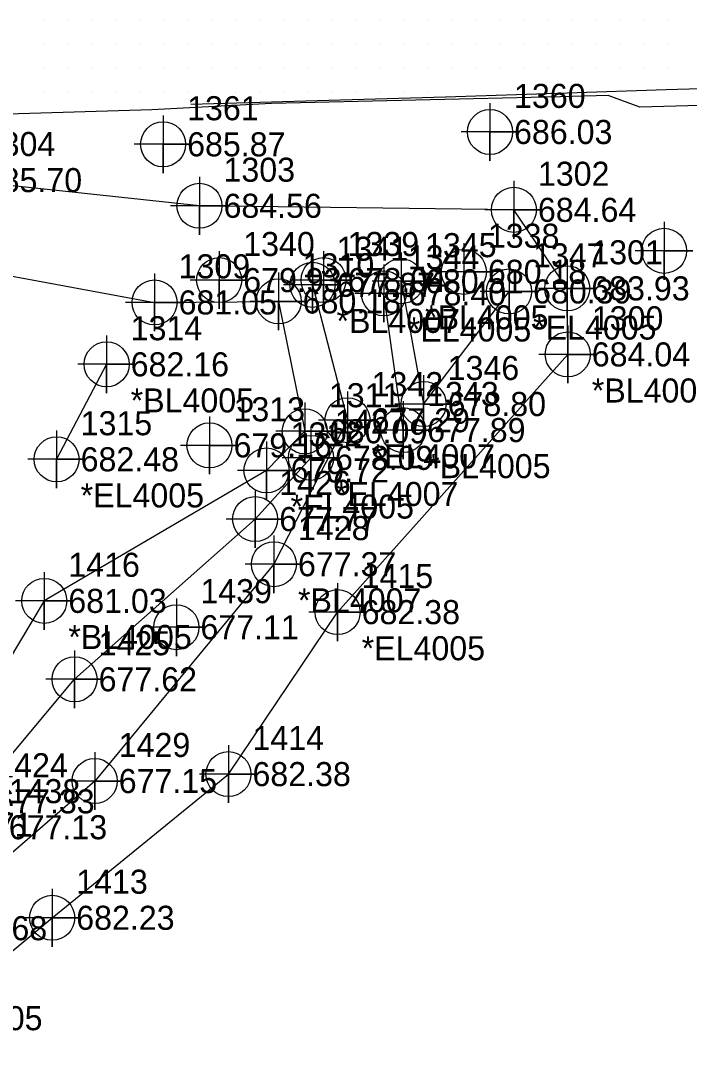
# Model space of a CAD drawing. Extents: x 1755643 to 1760494, y 736519 to 737621.
# Drawn here: x 1759051.4 to 1759120.9, y 736912 to 737018.8 of the extents above; entities that cross this region are included whole.
import ezdxf

# ---------------------------------------------------------------- set-up
doc = ezdxf.new("R2010")
doc.units = 0
for name, color, linetype in [('Exist Horizontal Alignment Curve and Spiral Data', 7, 'Continuous'), ('Exist Horizontal Alignment Direction Label', 7, 'Continuous'), ('Exist Roads EOT', 7, 'Continuous'), ('Exist Utilities Sanitary Sewer UG Line', 7, 'Continuous'), ('Old_Level_3', 7, 'Continuous'), ('Prop Conc 5in Monolithic Keyed In Island', 7, 'Continuous'), ('Prop Corridor Linear Feature', 7, 'Continuous'), ('Prop EOT Dash', 7, 'Continuous'), ('Prop Horizontal Alignment Station Label', 7, 'Continuous'), ('Prop Horizontal Alignment Tick Label', 7, 'Continuous'), ('Prop Horizontal Alignment Tick Large', 7, 'Continuous'), ('Prop Horizontal Alignment Tick Small', 7, 'Continuous'), ('Prop Lane Lines', 7, 'Continuous'), ('Prop Paved Shoulder', 7, 'Continuous'), ('Prop Superelevation Label', 7, 'Continuous'), ('Prop Terminator CELL', 7, 'Continuous'), ('Scratch_Level_1', 7, 'Continuous'), ('Scratch_Level_2', 7, 'Continuous'), ('Scratch_Level_5', 7, 'Continuous'), ('Scratch_Level_9', 7, 'Continuous')]:
    doc.layers.add(name, color=color, linetype=linetype)

msp = doc.modelspace()

# ---------------------------------------------------------------- linework, layer by layer
at = {"layer": 'Exist Horizontal Alignment Curve and Spiral Data'}
for points in [[(1759100.17, 737010.17), (1759100.17, 737004.17), (1759100.17, 737007.17), (1759103.17, 737007.17), (1759097.17, 737007.17)], [(1759066.19, 737008.89), (1759066.19, 737002.89), (1759066.19, 737005.89), (1759069.19, 737005.89), (1759063.19, 737005.89)], [(1759118.27, 736997.82), (1759118.27, 736991.82), (1759118.27, 736994.82), (1759121.27, 736994.82), (1759115.27, 736994.82)], [(1759097.45, 736995.63), (1759097.45, 736989.63), (1759097.45, 736992.63), (1759100.45, 736992.63), (1759094.45, 736992.63)], [(1759072.02, 736994.78), (1759072.02, 736988.78), (1759072.02, 736991.78), (1759075.02, 736991.78), (1759069.02, 736991.78)], [(1759071.01, 736977.61), (1759071.01, 736971.61), (1759071.01, 736974.61), (1759074.01, 736974.61), (1759068.01, 736974.61)]]:
    msp.add_lwpolyline(points, dxfattribs=at)
for centre in [(1759100.17, 737007.17), (1759066.19, 737005.89), (1759118.27, 736994.82), (1759097.45, 736992.63), (1759072.02, 736991.78), (1759071.01, 736974.61)]:
    msp.add_circle(centre, 2.34, dxfattribs=at)
at = {"layer": 'Prop Corridor Linear Feature'}
msp.add_lwpolyline([(1759145.67, 737011.05), (1759130.72, 737010.15), (1759115.74, 737009.75), (1759112.46, 737010.95), (1759107.45, 737010.81)], dxfattribs=at)
at = {"layer": 'Prop Horizontal Alignment Station Label'}
for points in [[(1759082.87, 736994.78), (1759082.87, 736988.78), (1759082.87, 736991.78), (1759085.87, 736991.78), (1759079.87, 736991.78)], [(1759067.57, 736958.71), (1759067.57, 736952.71), (1759067.57, 736955.71), (1759070.57, 736955.71), (1759064.57, 736955.71)]]:
    msp.add_lwpolyline(points, dxfattribs=at)
for centre in [(1759082.87, 736991.78), (1759067.57, 736955.71)]:
    msp.add_circle(centre, 2.34, dxfattribs=at)
at = {"layer": 'Prop Horizontal Alignment Tick Small'}
for points in [[(1759081.72, 736994.29), (1759081.72, 736988.29), (1759081.72, 736991.29), (1759084.72, 736991.29), (1759078.72, 736991.29)], [(1759085.36, 736980.22), (1759085.36, 736974.22), (1759085.36, 736977.22), (1759088.36, 736977.22), (1759082.36, 736977.22)], [(1759081.56, 736976.31), (1759081.56, 736970.31), (1759081.56, 736973.31), (1759084.56, 736973.31), (1759078.56, 736973.31)], [(1759075.76, 736969.95), (1759075.76, 736963.95), (1759075.76, 736966.95), (1759078.76, 736966.95), (1759072.76, 736966.95)], [(1759077.71, 736965.26), (1759077.71, 736959.26), (1759077.71, 736962.26), (1759080.71, 736962.26), (1759074.71, 736962.26)], [(1759056.99, 736953.3), (1759056.99, 736947.3), (1759056.99, 736950.3), (1759059.99, 736950.3), (1759053.99, 736950.3)], [(1759059.08, 736942.73), (1759059.08, 736936.73), (1759059.08, 736939.73), (1759062.08, 736939.73), (1759056.08, 736939.73)]]:
    msp.add_lwpolyline(points, dxfattribs=at)
for centre in [(1759081.72, 736991.29), (1759085.36, 736977.22), (1759081.56, 736973.31), (1759075.76, 736966.95), (1759077.71, 736962.26), (1759056.99, 736950.3), (1759059.08, 736939.73)]:
    msp.add_circle(centre, 2.34, dxfattribs=at)
at = {"layer": 'Prop Lane Lines'}
for points in [[(1759069.97, 737002.5), (1759069.97, 736996.5), (1759069.97, 736999.5), (1759072.97, 736999.5), (1759066.97, 736999.5)], [(1759102.65, 737002.08), (1759102.65, 736996.08), (1759102.65, 736999.08), (1759105.65, 736999.08), (1759099.65, 736999.08)], [(1759090.92, 736994.66), (1759090.92, 736988.66), (1759090.92, 736991.66), (1759093.92, 736991.66), (1759087.92, 736991.66)], [(1759102.15, 736993.6), (1759102.15, 736987.6), (1759102.15, 736990.6), (1759105.15, 736990.6), (1759099.15, 736990.6)], [(1759108.2, 736993.92), (1759108.2, 736987.92), (1759108.2, 736990.92), (1759111.2, 736990.92), (1759105.2, 736990.92)], [(1759065.3, 736992.46), (1759065.3, 736986.46), (1759065.3, 736989.46), (1759068.3, 736989.46), (1759062.3, 736989.46)], [(1759078.2, 736992.57), (1759078.2, 736986.57), (1759078.2, 736989.57), (1759081.2, 736989.57), (1759075.2, 736989.57)], [(1759089.13, 736993.4), (1759089.13, 736987.4), (1759089.13, 736990.4), (1759092.13, 736990.4), (1759086.13, 736990.4)], [(1759108.25, 736987.06), (1759108.25, 736981.06), (1759108.25, 736984.06), (1759111.25, 736984.06), (1759105.25, 736984.06)], [(1759060.32, 736986.03), (1759060.32, 736980.03), (1759060.32, 736983.03), (1759063.32, 736983.03), (1759057.32, 736983.03)], [(1759093.27, 736981.9), (1759093.27, 736975.9), (1759093.27, 736978.9), (1759096.27, 736978.9), (1759090.27, 736978.9)], [(1759080.92, 736979.07), (1759080.92, 736973.07), (1759080.92, 736976.07), (1759083.92, 736976.07), (1759077.92, 736976.07)], [(1759091.14, 736979.19), (1759091.14, 736973.19), (1759091.14, 736976.19), (1759094.14, 736976.19), (1759088.14, 736976.19)], [(1759055.12, 736976.16), (1759055.12, 736970.16), (1759055.12, 736973.16), (1759058.12, 736973.16), (1759052.12, 736973.16)], [(1759076.94, 736975), (1759076.94, 736969), (1759076.94, 736972), (1759079.94, 736972), (1759073.94, 736972)], [(1759053.84, 736961.45), (1759053.84, 736955.45), (1759053.84, 736958.45), (1759056.84, 736958.45), (1759050.84, 736958.45)], [(1759084.33, 736960.28), (1759084.33, 736954.28), (1759084.33, 736957.28), (1759087.33, 736957.28), (1759081.33, 736957.28)], [(1759072.98, 736943.45), (1759072.98, 736937.45), (1759072.98, 736940.45), (1759075.98, 736940.45), (1759069.98, 736940.45)], [(1759054.66, 736928.52), (1759054.66, 736922.52), (1759054.66, 736925.52), (1759057.66, 736925.52), (1759051.66, 736925.52)]]:
    msp.add_lwpolyline(points, dxfattribs=at)
for centre in [(1759069.97, 736999.5), (1759102.65, 736999.08), (1759090.92, 736991.66), (1759089.13, 736990.4), (1759102.15, 736990.6), (1759108.2, 736990.92), (1759065.3, 736989.46), (1759078.2, 736989.57), (1759108.25, 736984.06), (1759060.32, 736983.03), (1759093.27, 736978.9), (1759091.14, 736976.19), (1759080.92, 736976.07), (1759055.12, 736973.16), (1759076.94, 736972), (1759053.84, 736958.45), (1759084.33, 736957.28), (1759072.98, 736940.45), (1759054.66, 736925.52)]:
    msp.add_circle(centre, 2.34, dxfattribs=at)
at = {"layer": 'Prop Terminator CELL'}
msp.add_line((1759081.72, 736991.29), (1759085.36, 736977.22), dxfattribs=at)
for points in [[(1759085.36, 736977.22), (1759077.71, 736962.26), (1759059.08, 736939.73), (1759041.42, 736924.44), (1759026.52, 736914.34), (1759015.82, 736906.96), (1758998.09, 736890.9)], [(1758994.95, 736898.07), (1759015.63, 736913.87), (1759033.04, 736926.27), (1759046.35, 736937.62), (1759056.99, 736950.3), (1759075.76, 736966.95), (1759081.56, 736973.31)]]:
    msp.add_lwpolyline(points, dxfattribs=at)
at = {"layer": 'Scratch_Level_1'}
for points in [[(1759107.45, 737010.81), (1759092.46, 737010.47), (1759077.46, 737010.12), (1759065.02, 737009.48)], [(1759065.02, 737009.48), (1759050.02, 737009.03), (1759029.86, 737008.36), (1759020.04, 737008.1), (1759005.05, 737007.39), (1758990.06, 737006.95), (1758975.04, 737006.42), (1758960.05, 737006), (1758945.06, 737005.7), (1758930.12, 737005.23), (1758915.13, 737004.67), (1758900.15, 737004.23), (1758885.1, 737003.7), (1758867.07, 737003.45)]]:
    msp.add_lwpolyline(points, dxfattribs=at)
at = {"layer": 'Scratch_Level_2'}
for p, q in [((1759053.75, 737018.75), (1759053.75, 737018.75)), ((1759056.25, 737018.75), (1759056.25, 737018.75)), ((1759058.75, 737018.75), (1759058.75, 737018.75)), ((1759061.25, 737018.75), (1759061.25, 737018.75)), ((1759063.75, 737018.75), (1759063.75, 737018.75)), ((1759066.25, 737018.75), (1759066.25, 737018.75)), ((1759068.75, 737018.75), (1759068.75, 737018.75)), ((1759071.25, 737018.75), (1759071.25, 737018.75)), ((1759073.75, 737018.75), (1759073.75, 737018.75)), ((1759076.25, 737018.75), (1759076.25, 737018.75)), ((1759078.75, 737018.75), (1759078.75, 737018.75)), ((1759081.25, 737018.75), (1759081.25, 737018.75)), ((1759083.75, 737018.75), (1759083.75, 737018.75)), ((1759086.25, 737018.75), (1759086.25, 737018.75)), ((1759088.75, 737018.75), (1759088.75, 737018.75)), ((1759091.25, 737018.75), (1759091.25, 737018.75)), ((1759093.75, 737018.75), (1759093.75, 737018.75)), ((1759096.25, 737018.75), (1759096.25, 737018.75)), ((1759098.75, 737018.75), (1759098.75, 737018.75)), ((1759101.25, 737018.75), (1759101.25, 737018.75)), ((1759103.75, 737018.75), (1759103.75, 737018.75)), ((1759106.25, 737018.75), (1759106.25, 737018.75)), ((1759108.75, 737018.75), (1759108.75, 737018.75)), ((1759111.25, 737018.75), (1759111.25, 737018.75)), ((1759113.75, 737018.75), (1759113.75, 737018.75)), ((1759116.25, 737018.75), (1759116.25, 737018.75)), ((1759118.75, 737018.75), (1759118.75, 737018.75)), ((1759053.75, 737016.25), (1759053.75, 737016.25)), ((1759056.25, 737016.25), (1759056.25, 737016.25)), ((1759058.75, 737016.25), (1759058.75, 737016.25)), ((1759061.25, 737016.25), (1759061.25, 737016.25)), ((1759063.75, 737016.25), (1759063.75, 737016.25)), ((1759066.25, 737016.25), (1759066.25, 737016.25)), ((1759068.75, 737016.25), (1759068.75, 737016.25)), ((1759071.25, 737016.25), (1759071.25, 737016.25)), ((1759073.75, 737016.25), (1759073.75, 737016.25)), ((1759076.25, 737016.25), (1759076.25, 737016.25)), ((1759078.75, 737016.25), (1759078.75, 737016.25)), ((1759081.25, 737016.25), (1759081.25, 737016.25)), ((1759083.75, 737016.25), (1759083.75, 737016.25)), ((1759086.25, 737016.25), (1759086.25, 737016.25)), ((1759088.75, 737016.25), (1759088.75, 737016.25)), ((1759091.25, 737016.25), (1759091.25, 737016.25)), ((1759093.75, 737016.25), (1759093.75, 737016.25)), ((1759096.25, 737016.25), (1759096.25, 737016.25)), ((1759098.75, 737016.25), (1759098.75, 737016.25)), ((1759101.25, 737016.25), (1759101.25, 737016.25)), ((1759103.75, 737016.25), (1759103.75, 737016.25)), ((1759106.25, 737016.25), (1759106.25, 737016.25)), ((1759108.75, 737016.25), (1759108.75, 737016.25)), ((1759111.25, 737016.25), (1759111.25, 737016.25)), ((1759113.75, 737016.25), (1759113.75, 737016.25)), ((1759116.25, 737016.25), (1759116.25, 737016.25)), ((1759118.75, 737016.25), (1759118.75, 737016.25)), ((1759053.75, 737013.75), (1759053.75, 737013.75)), ((1759056.25, 737013.75), (1759056.25, 737013.75)), ((1759058.75, 737013.75), (1759058.75, 737013.75)), ((1759061.25, 737013.75), (1759061.25, 737013.75)), ((1759063.75, 737013.75), (1759063.75, 737013.75)), ((1759066.25, 737013.75), (1759066.25, 737013.75)), ((1759068.75, 737013.75), (1759068.75, 737013.75)), ((1759071.25, 737013.75), (1759071.25, 737013.75)), ((1759073.75, 737013.75), (1759073.75, 737013.75)), ((1759076.25, 737013.75), (1759076.25, 737013.75)), ((1759078.75, 737013.75), (1759078.75, 737013.75)), ((1759081.25, 737013.75), (1759081.25, 737013.75)), ((1759083.75, 737013.75), (1759083.75, 737013.75)), ((1759086.25, 737013.75), (1759086.25, 737013.75)), ((1759088.75, 737013.75), (1759088.75, 737013.75)), ((1759091.25, 737013.75), (1759091.25, 737013.75)), ((1759093.75, 737013.75), (1759093.75, 737013.75)), ((1759096.25, 737013.75), (1759096.25, 737013.75)), ((1759098.75, 737013.75), (1759098.75, 737013.75)), ((1759101.25, 737013.75), (1759101.25, 737013.75)), ((1759103.75, 737013.75), (1759103.75, 737013.75)), ((1759106.25, 737013.75), (1759106.25, 737013.75)), ((1759108.75, 737013.75), (1759108.75, 737013.75)), ((1759111.25, 737013.75), (1759111.25, 737013.75)), ((1759113.75, 737013.75), (1759113.75, 737013.75)), ((1759116.25, 737013.75), (1759116.25, 737013.75)), ((1759118.75, 737013.75), (1759118.75, 737013.75)), ((1759053.75, 737011.25), (1759053.75, 737011.25)), ((1759056.25, 737011.25), (1759056.25, 737011.25)), ((1759058.75, 737011.25), (1759058.75, 737011.25)), ((1759061.25, 737011.25), (1759061.25, 737011.25)), ((1759063.75, 737011.25), (1759063.75, 737011.25)), ((1759066.25, 737011.25), (1759066.25, 737011.25)), ((1759068.75, 737011.25), (1759068.75, 737011.25)), ((1759071.25, 737011.25), (1759071.25, 737011.25)), ((1759073.75, 737011.25), (1759073.75, 737011.25)), ((1759076.25, 737011.25), (1759076.25, 737011.25)), ((1759078.75, 737011.25), (1759078.75, 737011.25)), ((1759081.25, 737011.25), (1759081.25, 737011.25)), ((1759083.75, 737011.25), (1759083.75, 737011.25)), ((1759086.25, 737011.25), (1759086.25, 737011.25)), ((1759088.75, 737011.25), (1759088.75, 737011.25)), ((1759091.25, 737011.25), (1759091.25, 737011.25)), ((1759093.75, 737011.25), (1759093.75, 737011.25))]:
    msp.add_line(p, q, dxfattribs=at)
at = {"layer": 'Scratch_Level_5'}
msp.add_lwpolyline([(1759171.82, 737012.72), (1759163.49, 737012.68), (1759153.29, 737012.42), (1759142, 737012.2), (1759130.39, 737011.89), (1759118.48, 737011.54), (1759108.2, 737011.22), (1759095.54, 737010.79), (1759083.43, 737010.44), (1759069.08, 737010.03)], dxfattribs=at)
at = {"layer": 'Scratch_Level_9'}
for p, q in [((1759091.14, 736976.19), (1759089.13, 736990.4)), ((1759060.32, 736983.03), (1759055.12, 736973.16))]:
    msp.add_line(p, q, dxfattribs=at)
for points in [[(1759108.25, 736984.06), (1759108.2, 736990.92), (1759102.65, 736999.08), (1759069.97, 736999.5), (1759045.05, 737002.17), (1759017.77, 737001.21), (1759002.7, 737002.72)], [(1759003.11, 736993.2), (1759036.81, 736994.71), (1759065.3, 736989.46), (1759078.2, 736989.57), (1759080.92, 736976.07), (1759076.94, 736972)], [(1759090.92, 736991.66), (1759093.27, 736978.9), (1759102.15, 736990.6)], [(1759012.11, 736888.34), (1759033.39, 736907.78), (1759054.66, 736925.52), (1759072.98, 736940.45), (1759084.33, 736957.28), (1759108.25, 736984.06)], [(1759076.94, 736972), (1759053.84, 736958.45), (1759039.9, 736935.19), (1759028.09, 736925.01), (1759009.01, 736912.95), (1758991.46, 736899.66)]]:
    msp.add_lwpolyline(points, dxfattribs=at)

# ---------------------------------------------------------------- texts
at = {"layer": 'Exist Horizontal Alignment Direction Label'}
for s, p in [('*BL4005', (1759093.42, 736986.66)), ('*EL4005', (1759104.65, 736985.6)), ('*EL4005', (1759091.63, 736985.4)), ('*BL4005', (1759110.75, 736979.06)), ('*BL4005', (1759062.82, 736978.03)), ('*BL4005', (1759093.64, 736971.2)), ('*EL4005', (1759057.62, 736968.16)), ('*EL4005', (1759079.44, 736967)), ('*BL4005', (1759056.34, 736953.45)), ('*EL4005', (1759086.83, 736952.28)), ('*EL4005', (1759040.83, 736913.84))]:
    msp.add_text(s, height=2.5, dxfattribs=at).set_placement(p)
at = {"layer": 'Exist Roads EOT'}
for s, p in [('1360', (1759102.67, 737009.67)), ('1361', (1759068.69, 737008.39)), ('1340', (1759074.52, 736994.28)), ('1338', (1759099.95, 736995.14)), ('1313', (1759073.51, 736977.11))]:
    msp.add_text(s, height=2.5, dxfattribs=at).set_placement(p)
at = {"layer": 'Exist Utilities Sanitary Sewer UG Line'}
for s, p in [('677.87', (1759084.22, 736990.04)), ('677.29', (1759087.86, 736975.97)), ('678.09', (1759084.06, 736972.06)), ('677.77', (1759078.26, 736965.7)), ('677.37', (1759080.21, 736961.01)), ('677.62', (1759059.49, 736949.05)), ('677.15', (1759061.58, 736938.48)), ('677.33', (1759048.85, 736936.37)), ('677.68', (1759043.92, 736923.19))]:
    msp.add_text(s, height=2.5, dxfattribs=at).set_placement(p)
at = {"layer": 'Old_Level_3'}
for s, p in [('685.70', (1759047.55, 737000.92)), ('684.56', (1759072.47, 736998.25)), ('684.64', (1759105.15, 736997.83)), ('680.51', (1759093.42, 736990.41)), ('678.40', (1759091.63, 736989.15)), ('680.39', (1759104.65, 736989.35)), ('683.93', (1759110.7, 736989.67)), ('681.05', (1759067.8, 736988.21)), ('680.18', (1759080.7, 736988.32)), ('684.04', (1759110.75, 736982.81)), ('682.16', (1759062.82, 736981.78)), ('678.80', (1759095.77, 736977.65)), ('677.89', (1759093.64, 736974.95)), ('680.09', (1759083.42, 736974.82)), ('682.48', (1759057.62, 736971.91)), ('679.72', (1759079.44, 736970.75)), ('681.03', (1759056.34, 736957.2)), ('682.38', (1759086.83, 736956.03)), ('682.38', (1759075.48, 736939.2)), ('680.71', (1759042.4, 736933.94)), ('682.23', (1759057.16, 736924.27))]:
    msp.add_text(s, height=2.5, dxfattribs=at).set_placement(p)
at = {"layer": 'Prop Conc 5in Monolithic Keyed In Island'}
for s, p in [('1341', (1759084.22, 736993.79)), ('1342', (1759087.86, 736979.72)), ('1427', (1759084.06, 736975.81)), ('1426', (1759078.26, 736969.45)), ('1428', (1759080.21, 736964.76)), ('1425', (1759059.49, 736952.8)), ('1429', (1759061.58, 736942.23)), ('1424', (1759048.85, 736940.12))]:
    msp.add_text(s, height=2.5, dxfattribs=at).set_placement(p)
at = {"layer": 'Prop EOT Dash'}
for s, p in [('1304', (1759047.55, 737004.67)), ('1303', (1759072.47, 737002)), ('1302', (1759105.15, 737001.58)), ('1345', (1759093.42, 736994.16)), ('1347', (1759104.65, 736993.1)), ('1301', (1759110.7, 736993.42)), ('1310', (1759080.7, 736992.07)), ('1344', (1759091.63, 736992.9)), ('1309', (1759067.8, 736991.96)), ('1300', (1759110.75, 736986.56)), ('1314', (1759062.82, 736985.53)), ('1346', (1759095.77, 736981.4)), ('1311', (1759083.42, 736978.57)), ('1343', (1759093.64, 736978.7)), ('1315', (1759057.62, 736975.66)), ('1312', (1759079.44, 736974.5)), ('1416', (1759056.34, 736960.95)), ('1415', (1759086.83, 736959.78)), ('1414', (1759075.48, 736942.95)), ('1413', (1759057.16, 736928.02))]:
    msp.add_text(s, height=2.5, dxfattribs=at).set_placement(p)
at = {"layer": 'Prop Horizontal Alignment Tick Label'}
for s, p in [('1339', (1759085.37, 736994.28)), ('1439', (1759070.07, 736958.21)), ('1438', (1759050.15, 736937.43))]:
    msp.add_text(s, height=2.5, dxfattribs=at).set_placement(p)
at = {"layer": 'Prop Horizontal Alignment Tick Large'}
for s, p in [('678.04', (1759085.37, 736990.53)), ('677.11', (1759070.07, 736954.46)), ('677.13', (1759050.15, 736933.68))]:
    msp.add_text(s, height=2.5, dxfattribs=at).set_placement(p)
at = {"layer": 'Prop Paved Shoulder'}
for s, p in [('686.03', (1759102.67, 737005.92)), ('685.87', (1759068.69, 737004.64)), ('680.18', (1759099.95, 736991.39)), ('679.93', (1759074.52, 736990.53)), ('679.16', (1759073.51, 736973.36))]:
    msp.add_text(s, height=2.5, dxfattribs=at).set_placement(p)
at = {"layer": 'Prop Superelevation Label'}
for s, p in [('*BL4007', (1759084.22, 736986.29)), ('*EL4007', (1759087.86, 736972.22)), ('*EL4007', (1759084.06, 736968.31)), ('*BL4007', (1759080.21, 736957.26))]:
    msp.add_text(s, height=2.5, dxfattribs=at).set_placement(p)

doc.saveas('drawing.dxf')
